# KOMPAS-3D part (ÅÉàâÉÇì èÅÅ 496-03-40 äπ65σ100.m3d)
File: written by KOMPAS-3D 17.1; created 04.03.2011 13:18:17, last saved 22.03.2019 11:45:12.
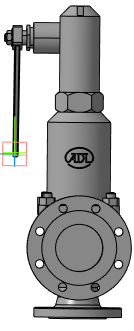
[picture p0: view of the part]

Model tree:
1. Плоскость XY
2. Плоскость ZX
3. Плоскость ZY
4. Ось X
5. Ось Y
6. Ось Z
7. Начало координат
8. Операция без истории:2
